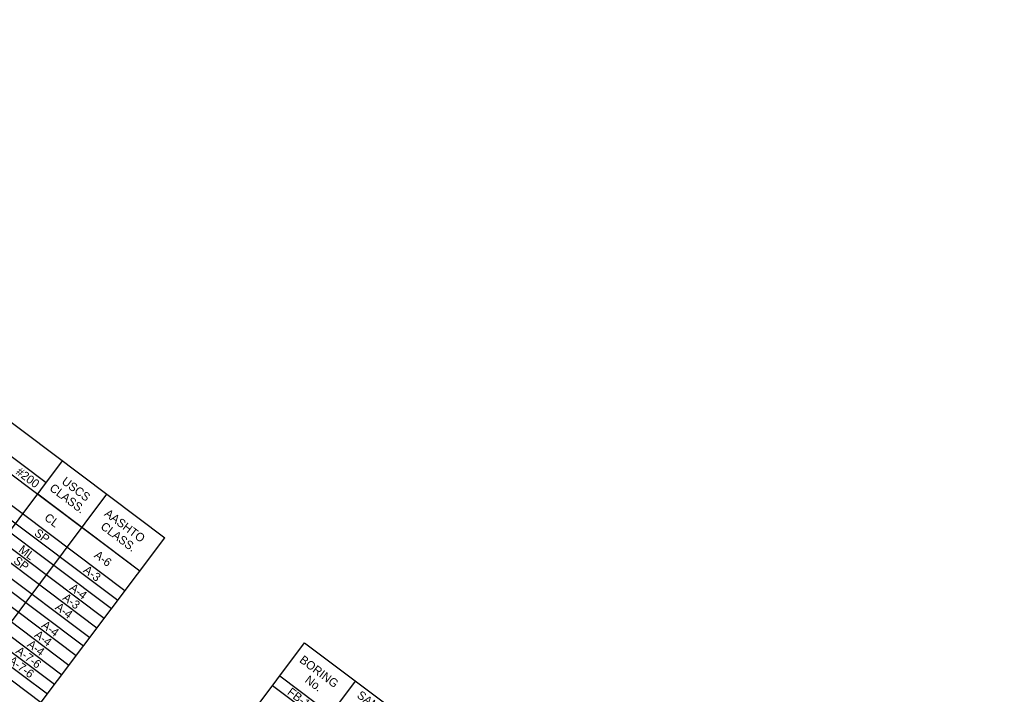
# Model space of a CAD drawing. Extents: x 627484.2 to 627517.5, y 367968.7 to 367996.9.
# Drawn here: x 627511.18 to 627517.5, y 367977.38 to 367981.76 of the extents above; entities that cross this region are included whole.
import ezdxf

# ---------------------------------------------------------------- set-up
doc = ezdxf.new("R2010")
doc.units = 0
doc.layers.add('Default', color=7, linetype='Continuous')
doc.layers.add('R_Survey Control', color=7, linetype='Continuous')

msp = doc.modelspace()

# ---------------------------------------------------------------- linework, layer by layer
at = {"layer": 'Default'}
for p, q in [((627507.6468, 367981.7554), (627512.1221, 367978.3948)), ((627507.4858, 367981.5409), (627511.9611, 367978.1804)), ((627507.3424, 367981.3499), (627511.8177, 367977.9894)), ((627507.3014, 367981.2954), (627511.7767, 367977.9348)), ((627507.2546, 367981.233), (627511.7298, 367977.8725)), ((627507.2078, 367981.1706), (627511.683, 367977.8101)), ((627507.1609, 367981.1082), (627511.6362, 367977.7477)), ((627507.1199, 367981.0537), (627511.5952, 367977.6932)), ((627507.0731, 367980.9913), (627511.5483, 367977.6308)), ((627507.0263, 367980.9289), (627511.5015, 367977.5684)), ((627506.9794, 367980.8665), (627511.4547, 367977.506)), ((627506.9326, 367980.8042), (627511.4078, 367977.4437)), ((627506.8858, 367980.7418), (627511.361, 367977.3813)), ((627506.8448, 367980.6872), (627511.32, 367977.3267)), ((627509.7635, 367979.9465), (627511.354, 367978.7521)), ((627510.6092, 367978.9944), (627511.8645, 367978.0518)), ((627509.6972, 367976.5457), (627511.4594, 367978.8925)), ((627510.577, 367977.1165), (627511.7479, 367978.6759)), ((627511.2984, 367978.6781), (627511.9611, 367978.1804)), ((627510.3599, 367976.0481), (627512.1221, 367978.3948)), ((627511.2411, 367975.3315), (627513.0296, 367977.7134)), ((627513.0296, 367977.7134), (627517.5049, 367974.3529)), ((627512.8686, 367977.499), (627517.3439, 367974.1385)), ((627511.5724, 367975.0827), (627513.361, 367977.4646)), ((627512.8218, 367977.4366), (627517.297, 367974.0761))]:
    msp.add_line(p, q, dxfattribs=at)
at = {"layer": 'R_Survey Control'}
msp.add_line((627513.0296, 367977.7134), (627513.0296, 367977.7134), dxfattribs=at)

# ---------------------------------------------------------------- texts
at = {"layer": 'Default'}
for s, p in [('#200', (627511.1522, 367978.8114)), ('USCS', (627511.4495, 367978.7494)), ('CLASS.', (627511.3703, 367978.7058)), ('AASHTO', (627511.7266, 367978.5414)), ('CL', (627511.337, 367978.5141)), ('CLASS.', (627511.7016, 367978.4569)), ('SP', (627511.2711, 367978.4142)), ('ML', (627511.1703, 367978.3071)), ('A-6', (627511.6599, 367978.2716)), ('SP', (627511.1365, 367978.2349)), ('A-3', (627511.5896, 367978.175)), ('A-4', (627511.5002, 367978.0593)), ('A-3', (627511.455, 367977.9957)), ('A-4', (627511.4066, 367977.9345)), ('A-4', (627511.3187, 367977.8176)), ('A-4', (627511.2719, 367977.7552)), ('A-7-6', (627511.1513, 367977.6507)), ('A-4', (627511.2251, 367977.6928)), ('A-7-6', (627511.1045, 367977.5883)), ('BORING', (627512.9915, 367977.5916)), ('No.', (627513.027, 367977.4617)), ('FB-14', (627512.9125, 367977.3829)), ('SAMPLE', (627513.3646, 367977.3629))]:
    msp.add_text(s, height=0.055, rotation=323.09678, dxfattribs=at).set_placement(p)

doc.saveas('drawing.dxf')
